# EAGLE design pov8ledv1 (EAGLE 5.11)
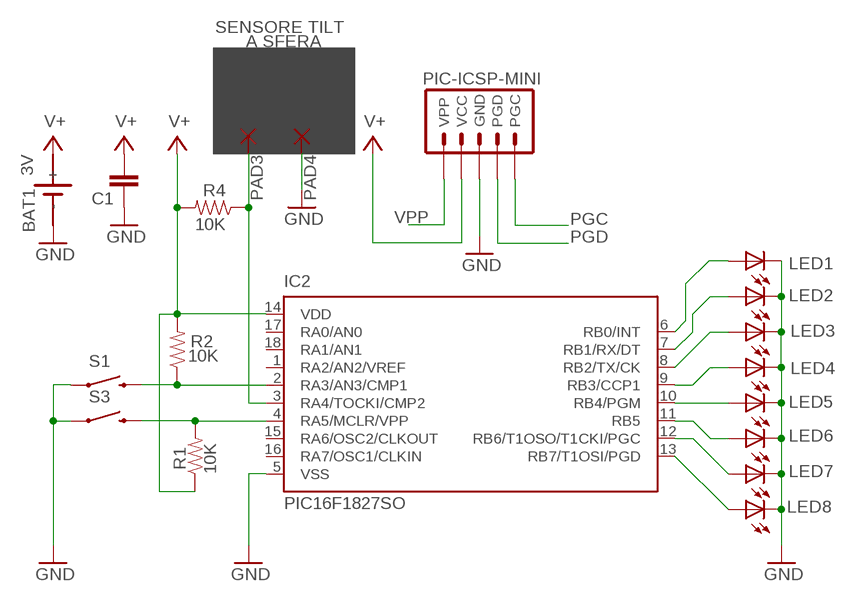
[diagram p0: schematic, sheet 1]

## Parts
BAT1  3V  SN2032  [SN2032]
C1  CAP0805  [0805]
IC2  PIC16F1827SO  PIC16F627SO  [SO-18W]
LED1  LEDCHIP-LED0805  [CHIP-LED0805]
LED2  LEDCHIP-LED0805  [CHIP-LED0805]
LED3  LEDCHIP-LED0805  [CHIP-LED0805]
LED4  LEDCHIP-LED0805  [CHIP-LED0805]
LED5  LEDCHIP-LED0805  [CHIP-LED0805]
LED6  LEDCHIP-LED0805  [CHIP-LED0805]
LED7  LEDCHIP-LED0805  [CHIP-LED0805]
LED8  LEDCHIP-LED0805  [CHIP-LED0805]
PAD3  SMD2  [SMD1,27-2,54]
PAD4  SMD2  [SMD1,27-2,54]
R1  10K  RESISTOR0805-RES  [0805]
R2  10K  RESISTOR0805-RES  [0805]
R4  10K  RESISTOR0805-RES  [0805]
S1  SWITCH-MOMENTARY-2-SMD-1101NE  [TACTILE-SWITCH-1101NE]
S3  SWITCH-MOMENTARY-2-SMD-1101NE  [TACTILE-SWITCH-1101NE]
U$1  PIC-ICSP-MINI  [PIC-ICSP-MINI]

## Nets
GND: BAT1.- C1.1 IC2.5(VSS) LED1.C LED2.C LED3.C LED4.C LED5.C LED6.C LED7.C LED8.C PAD4.1(P) S1.P$1 S3.P$1 U$1.3(GND)
N$1: IC2.6(RB0/INT) LED1.A
N$2: IC2.7(RB1/RX/DT) LED2.A
N$3: IC2.8(RB2/TX/CK) LED3.A
N$4: IC2.9(RB3/CCP1) LED4.A
N$5: IC2.10(RB4/PGM) LED5.A
N$6: IC2.11(RB5) LED6.A
N$10: IC2.2(RA3/AN3/CMP1) R2.1 S1.P$2
PGC: IC2.12(RB6/T1OSO/T1CKI/PGC) LED7.A U$1.5(PGC)
PGD: IC2.13(RB7/T1OSI/PGD) LED8.A U$1.4(PGD)
TILT: IC2.3(RA4/TOCKI/CMP2) PAD3.1(P) R4.1
V+: BAT1.+ C1.2 IC2.14(VDD) R1.1 R2.2 R4.2 U$1.2(VCC)
VPP: IC2.4(RA5/MCLR/VPP) R1.2 S3.P$2 U$1.1(VPP)
Unconnected: IC2.1(RA2/AN2/VREF) IC2.15(RA6/OSC2/CLKOUT) IC2.16(RA7/OSC1/CLKIN) IC2.17(RA0/AN0) IC2.18(RA1/AN1)

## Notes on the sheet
- SENSORE TILT
- A SFERA

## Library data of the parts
BAT1 = sn2032:SN2032: LI BATTERY
C1 = SparkFun:CAP: Capacitor
IC2 = microchip:PIC16F62*: FLASH-Based 8-Bit CMOS Microcontroller Source: http://ww1.microchip.com/downloads/en/DeviceDoc/40300C.pdf; MF: MICROCHIP; MPN: PIC16F627-04I/SO; OC_FARNELL: 9760296; OC_NEWARK: 19C7271
LED1-LED8 = led:LED: LED
PAD3 PAD4 = wirepad:SMD2: SMD PAD
R1 R2 R4 = SparkFun:RESISTOR: Resistor
S1 S3 = SparkFun:SWITCH-MOMENTARY-2
U$1 = SparkFun:PIC-ICSP-MINI: PIC-ICSP-Mini Miniature 5-pin connection for temporary programming of PICs. Use this device in your design to save space. Program the PIC with this adapter Spark Fun Electronics SKU : BOB-00194

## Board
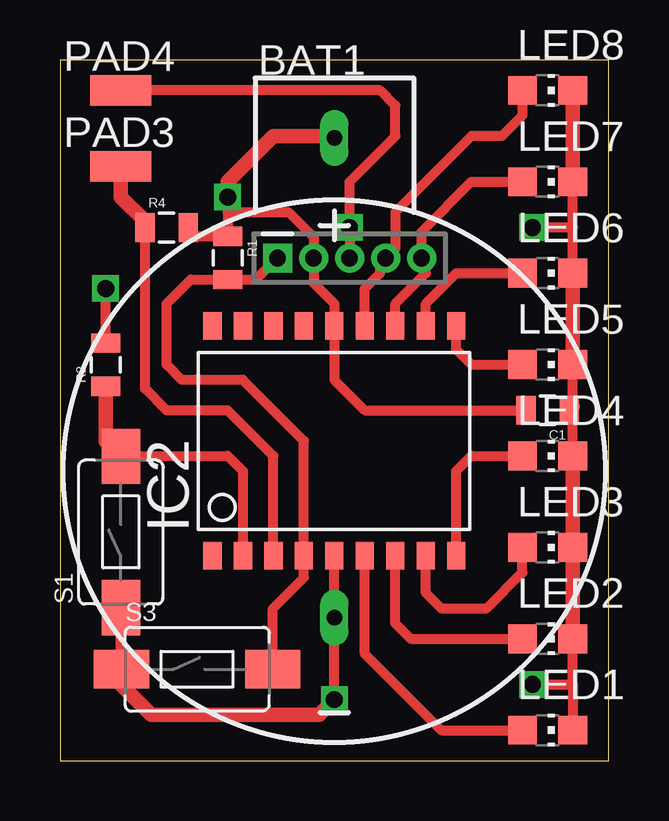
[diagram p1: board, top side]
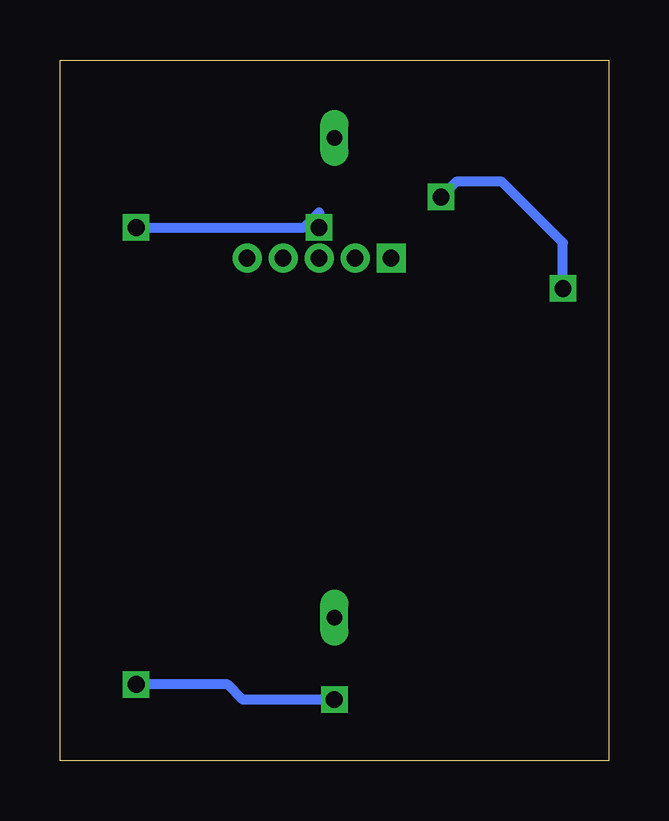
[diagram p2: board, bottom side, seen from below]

Size 22.86 x 29.21 mm. Coordinates in mm from the lower left corner, seen from the top.
Outline: 22.86,29.21 0,29.21 0,0 22.86,0 22.86,29.21
Copper layers (1*16): Top 0.035mm / dielectric 1.5mm / Bottom 0.035mm
Design rules "default": minimum track width 10mil, minimum drill 24mil, track to track 8mil, track to pad 8mil, pad to pad 8mil, via to via 8mil, smd to smd 8mil, copper to edge 40mil, drill to drill 8mil, minimum pad ring 10mil, minimum via ring 8mil, stop-mask expansion 4mil, vias tented up to drill 0mil, thermal gap 10mil

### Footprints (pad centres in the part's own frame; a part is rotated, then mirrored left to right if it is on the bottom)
SN2032 = drill 0.65 long: + 0,13.9; - 0,-6.1
0805 = smd 0.8 x 1.2: 1 -0.9,0; 2 0.9,0
SO-18W = smd 0.762 x 1.143: 1 -5.08,-4.788; 2 -3.81,-4.788; 3 -2.54,-4.788; 4 -1.27,-4.788; 5 0,-4.788; 6 1.27,-4.788; 7 2.54,-4.788; 8 3.81,-4.788; 9 5.08,-4.788; 10 5.08,4.788; 11 3.81,4.788; 12 2.54,4.788; 13 1.27,4.788; 14 0,4.788; 15 -1.27,4.788; 16 -2.54,4.788; 17 -3.81,4.788; 18 -5.08,4.788
CHIP-LED0805 = smd 1.2 x 1.2: A 0,-1.05; C 0,1.05
SMD1,27-2,54 = smd 1.27 x 2.54: 1 0,0
TACTILE-SWITCH-1101NE = smd 2.3 x 1.6: P$1 -3.15,0; P$2 3.15,0
PIC-ICSP-MINI = drill 0.7 square: 1 -3,0 | drill 0.7 round: 2 -1.5,0; 3 0,0; 4 1.5,0; 5 3,0

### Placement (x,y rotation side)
BAT1  11.43,12.06 0 top
C1  20.32,14.61 180 top
IC2  11.43,13.34 0 top
LED1  20.32,1.27 270 top
LED2  20.32,5.08 270 top
LED3  20.32,8.89 270 top
LED4  20.32,12.7 270 top
LED5  20.32,16.51 270 top
LED6  20.32,20.32 270 top
LED7  20.32,24.13 270 top
LED8  20.32,27.94 270 top
PAD3  2.54,24.77 270 top
PAD4  2.54,27.94 270 top
R1  6.99,20.95 270 top
R2  1.91,16.51 90 top
R4  4.45,22.23 0 top
S1  2.54,9.53 90 top
S3  5.71,3.81 0 top
U$1  12.06,20.95 0 top

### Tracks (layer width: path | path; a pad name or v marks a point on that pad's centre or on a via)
GND  (via drill 0.7)
  Top 0.406: C1.1 21.37,14.46 LED4.C | U$1.3 v12.06,22.23 12.06,24.13 13.97,26.04 13.97,27.3 13.34,27.94 PAD4.1 | 21.37,22.23 v19.68,22.23 | v11.43,2.54 BAT1.- IC2.5 | v19.68,3.17 21.37,3.17 | 2.54,3.83 S3.P$1 2.54,3.81 | 2.54,3.81 S1.P$1 | 2.54,3.17 2.54,3.81 | 21.37,3.17 LED2.C | 21.37,3.17 LED1.C | 21.37,14.76 LED5.C | LED6.C 21.37,22.23 | 21.37,22.23 LED7.C
  Top 0.61: C1.1 21.37,14.76 | 2.54,3.17 3.81,1.91 10.79,1.91 v11.43,2.54 | LED7.C LED8.C | LED5.C LED6.C | LED4.C LED3.C LED2.C
  Bottom 0.406: v11.43,2.54 15.24,2.54 15.88,3.17 v19.68,3.17 | v19.68,22.23 12.7,22.23 12.06,22.86 v12.06,22.23
N$1
  Top 0.406: IC2.6 12.7,4.45 15.88,1.27 LED1.A
N$2
  Top 0.406: IC2.7 13.97,5.71 14.61,5.08 LED2.A
N$3
  Top 0.406: LED3.A 19.27,7.84 17.78,6.35 15.88,6.35 15.24,6.99 IC2.8
N$4
  Top 0.406: LED4.A 17.14,12.7 16.51,12.06 IC2.9
N$5
  Top 0.406: IC2.10 16.51,17.14 17.14,16.51 LED5.A
N$6
  Top 0.406: IC2.11 15.24,19.05 16.51,20.32 LED6.A
N$10
  Top 0.406: IC2.2 7.62,12.06 6.99,12.7 2.56,12.7 S1.P$2 1.91,13.31
  Top 0.61: 1.91,13.31 R2.1
PGC
  Top 0.406: IC2.12 13.97,19.05 15.24,20.32 15.24,20.95 | LED7.A 17.14,24.13 15.06,22.05 15.06,21.13 15.24,20.95 | 15.24,20.95 U$1.5
PGD
  Top 0.406: IC2.13 12.7,19.68 13.34,20.32 13.34,20.73 U$1.4 13.97,21.36 13.97,22.86 17.14,26.04 18.41,26.04 19.27,26.89 LED8.A
TILT
  Top 0.406: IC2.3 8.89,12.7 6.99,14.61 4.45,14.61 3.54,15.51 3.54,21.59 R4.1 3.54,22.49
  Top 0.61: 3.54,22.49 2.54,23.5 PAD3.1
V+  (via drill 0.7)
  Top 0.406: R2.2 v1.91,19.68 | 11.36,26.04 10.79,26.04 | C1.2 12.7,14.61 11.43,15.88 IC2.14 11.43,19.05 10.56,19.91 U$1.2 10.56,21.82 9.53,22.86 6.99,22.86 | R4.2 5.71,21.86 R1.1 6.99,22.86 | 6.99,22.86 v6.99,23.5 6.99,24.13
  Top 0.61: 6.99,24.13 8.89,26.04 11.36,26.04 BAT1.+
  Bottom 0.406: v1.91,19.68 1.91,21.59 4.45,24.13 6.35,24.13 v6.99,23.5
VPP
  Top 0.406: S3.P$2 8.87,6.33 10.16,7.62 IC2.4 10.16,13.34 7.62,15.88 5.08,15.88 4.45,16.51 4.45,19.05 5.45,20.05 R1.2 8.16,20.05 U$1.1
